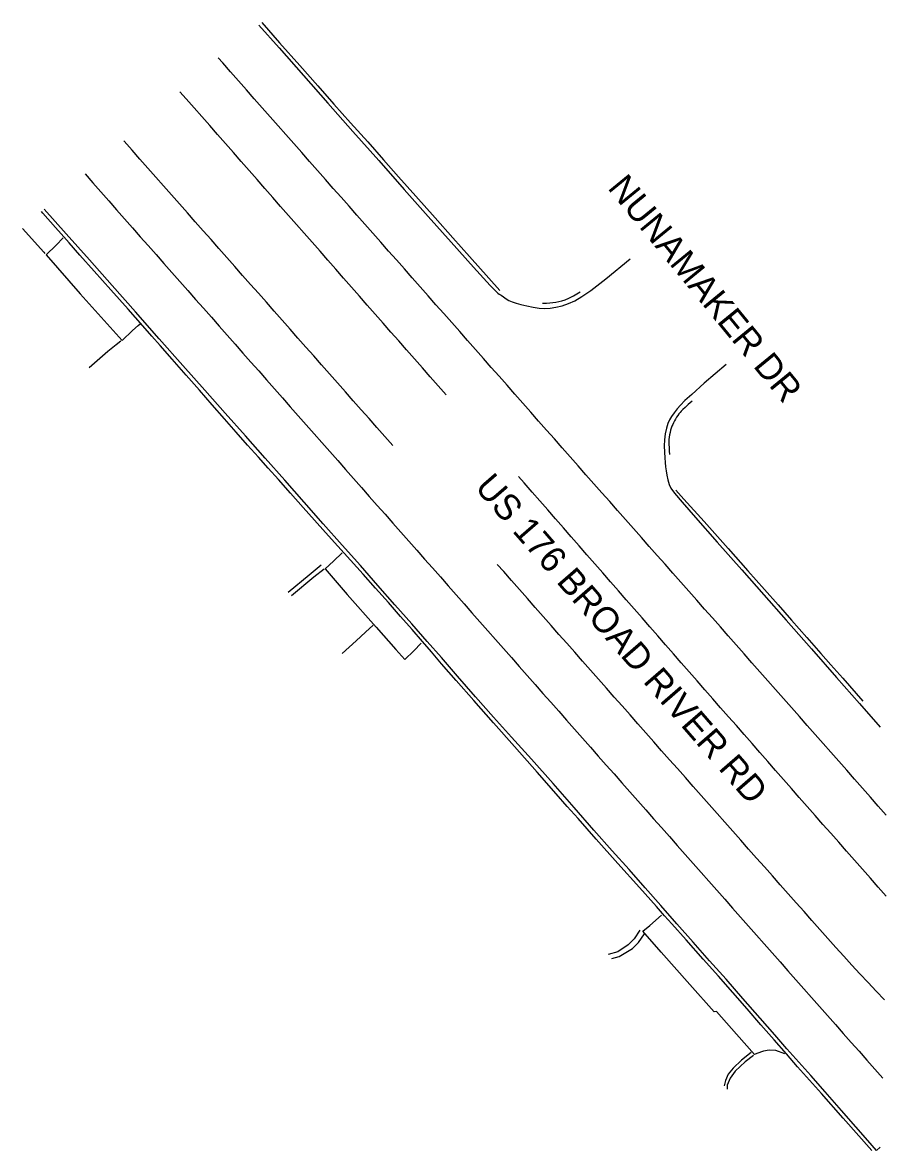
# Model space of a CAD drawing. Extents: x 1970211 to 1973046, y 801032 to 804001.
# Drawn here: x 1970210.9 to 1970390.1, y 803765.1 to 804001.2 of the extents above; entities that cross this region are included whole.
import ezdxf

# ---------------------------------------------------------------- set-up
doc = ezdxf.new("R2010")
doc.units = 0
for name, color, linetype in [('RD_EX_Conc', 7, 'Continuous'), ('RD_EX_Road', 7, 'Continuous'), ('RD_EX_Road_Paint', 7, 'Continuous'), ('RD_TX_RoadID', 7, 'Continuous')]:
    doc.layers.add(name, color=color, linetype=linetype)

msp = doc.modelspace()

# ---------------------------------------------------------------- linework, layer by layer
at = {"layer": 'RD_EX_Conc'}
for points in [[(1970261.01, 804001.2), (1970264.73, 803996.97), (1970268.97, 803992.18), (1970272.72, 803987.95), (1970276.12, 803984.12), (1970279.61, 803980.21), (1970283.19, 803976.2), (1970286.52, 803972.46), (1970289.65, 803968.92), (1970293.25, 803964.87), (1970297.29, 803960.31), (1970301.03, 803956.11), (1970304.48, 803952.22), (1970308.53, 803947.68), (1970310.84, 803945.11)], [(1970388.74, 803765.05), (1970382.78, 803771.78), (1970378.2, 803776.95), (1970373.21, 803782.59), (1970370.86, 803785.25), (1970368.3, 803788.19), (1970365.55, 803791.36), (1970362.62, 803794.69), (1970359.62, 803798.11), (1970356.62, 803801.53), (1970353.43, 803805.13), (1970349.88, 803809.13), (1970346.87, 803812.49), (1970345.35, 803814.19), (1970343.65, 803816.11), (1970340.08, 803820.11), (1970335.58, 803825.16), (1970331.03, 803830.26), (1970327.24, 803834.52), (1970324.97, 803837.08), (1970322.64, 803839.73), (1970318.64, 803844.28), (1970313.94, 803849.61), (1970309.51, 803854.61), (1970305.42, 803859.24), (1970301.72, 803863.46), (1970298.66, 803866.96), (1970296.53, 803869.45), (1970294.68, 803871.6), (1970292.51, 803874.12), (1970290.08, 803876.88), (1970287.51, 803879.81), (1970284.85, 803882.79), (1970282.21, 803885.71), (1970279.56, 803888.61), (1970276.92, 803891.56), (1970274.37, 803894.4), (1970272.04, 803897.02), (1970269.68, 803899.67), (1970267.05, 803902.65), (1970264.5, 803905.54), (1970262.35, 803907.93), (1970260.3, 803910.2), (1970258.04, 803912.75), (1970255.64, 803915.46), (1970253.19, 803918.26), (1970250.64, 803921.16), (1970247.96, 803924.2), (1970245.16, 803927.38), (1970242.25, 803930.69), (1970239.7, 803933.59), (1970237.98, 803935.57), (1970236.08, 803937.73), (1970232.99, 803941.19), (1970229.38, 803945.22), (1970225.93, 803949.12), (1970222.92, 803952.53), (1970220.64, 803955.11), (1970218.97, 803956.99), (1970217.8, 803958.29), (1970215.15, 803961.28), (1970214.85, 803961.62)], [(1970210.9, 803958.1), (1970215.36, 803953.1), (1970215.57, 803952.85)], [(1970219.39, 803956.14), (1970217.97, 803954.57), (1970215.82, 803952.57), (1970222.99, 803944.43), (1970231.73, 803934.64), (1970233.9, 803936.74), (1970235.08, 803937.76), (1970235.56, 803938.13)], [(1970319.78, 803942.42), (1970320.64, 803942.44), (1970321.34, 803942.49), (1970321.97, 803942.58), (1970322.6, 803942.67), (1970323.23, 803942.78), (1970323.86, 803942.95), (1970324.54, 803943.17), (1970325.29, 803943.48), (1970326.29, 803943.99), (1970327.7, 803944.84)], [(1970351.12, 803921.9), (1970350.3, 803921.2), (1970349.65, 803920.63), (1970349.17, 803920.18), (1970348.84, 803919.86), (1970348.6, 803919.59), (1970348.35, 803919.28), (1970348.11, 803918.93), (1970347.86, 803918.55), (1970347.63, 803918.16), (1970347.42, 803917.78), (1970347.23, 803917.42), (1970347.07, 803917.07), (1970346.91, 803916.71), (1970346.77, 803916.31), (1970346.63, 803915.88), (1970346.5, 803915.4), (1970346.39, 803914.91), (1970346.3, 803914.42), (1970346.26, 803913.92), (1970346.24, 803913.42), (1970346.25, 803912.88), (1970346.29, 803912.25), (1970346.34, 803911.53), (1970346.42, 803910.73)], [(1970347.74, 803903.3), (1970349.42, 803901.41), (1970353.62, 803896.72), (1970358.66, 803891.1), (1970362.82, 803886.42), (1970366.26, 803882.52), (1970369.12, 803879.27), (1970371.91, 803876.1), (1970375.13, 803872.47), (1970378.11, 803869.11), (1970380.18, 803866.76), (1970382.66, 803863.92), (1970386.9, 803859.09)], [(1970277.84, 803890.15), (1970276.04, 803888.45), (1970274.26, 803886.84), (1970278.85, 803881.44), (1970284.98, 803874.6), (1970289.04, 803869.96), (1970290.96, 803867.83), (1970292.81, 803869.69), (1970294.4, 803871.27)], [(1970266.53, 803881.97), (1970270.95, 803885.57), (1970273.45, 803887.67)], [(1970370.53, 803785.3), (1970368.68, 803785.96), (1970367.28, 803786.08), (1970366.1, 803785.85), (1970364.7, 803785.38), (1970364.22, 803785.13), (1970360.43, 803789.38), (1970356.2, 803794.15), (1970355.71, 803794.07), (1970350.62, 803799.8), (1970344.65, 803806.54), (1970340.77, 803810.98), (1970342.25, 803812.15), (1970344.68, 803814.31)], [(1970340.16, 803811.14), (1970339.01, 803809.39), (1970337.74, 803808.1), (1970335.55, 803806.62), (1970333.55, 803806.11)], [(1970363.98, 803784.91), (1970362.2, 803783.62), (1970360.14, 803781.68), (1970359.08, 803780.19), (1970358.49, 803778.7), (1970358.44, 803777.91)]]:
    msp.add_lwpolyline(points, dxfattribs=at)
at = {"layer": 'RD_EX_Road'}
for points in [[(1970260.41, 804000.67), (1970264.66, 803995.88), (1970269.73, 803990.14), (1970274.85, 803984.33), (1970280.09, 803978.39), (1970285.49, 803972.29), (1970290.83, 803966.28), (1970295.86, 803960.6), (1970300.66, 803955.21), (1970305.34, 803950.01), (1970308.86, 803946.15), (1970310.2, 803944.72), (1970310.45, 803944.52), (1970310.73, 803944.33), (1970311.1, 803944.09), (1970311.6, 803943.75), (1970312.18, 803943.37), (1970312.76, 803943.04), (1970313.43, 803942.74), (1970314.25, 803942.48), (1970315.26, 803942.2), (1970316.5, 803941.88), (1970317.81, 803941.59), (1970319.07, 803941.41), (1970320.26, 803941.35), (1970321.38, 803941.4), (1970322.55, 803941.59), (1970323.88, 803941.92), (1970325.26, 803942.39), (1970326.56, 803942.96), (1970328.04, 803943.82), (1970329.94, 803945.12), (1970333.04, 803947.54), (1970338.13, 803951.74)], [(1970390.5, 803765.74), (1970389.77, 803765.07), (1970387.94, 803767.13), (1970385.41, 803769.99), (1970382.38, 803773.43), (1970378.99, 803777.31), (1970375.99, 803780.71), (1970373.46, 803783.56), (1970370.99, 803786.35), (1970368.45, 803789.24), (1970365.38, 803792.75), (1970361.78, 803796.85), (1970358.23, 803800.88), (1970354.8, 803804.75), (1970351.36, 803808.63), (1970347.9, 803812.53), (1970344.54, 803816.33), (1970341.28, 803820.04), (1970337.92, 803823.84), (1970334.41, 803827.79), (1970330.57, 803832.13), (1970326.39, 803836.88), (1970321.99, 803841.86), (1970317.48, 803846.96), (1970313.33, 803851.6), (1970309.53, 803855.79), (1970305.75, 803860.05), (1970301.97, 803864.38), (1970298.61, 803868.24), (1970295.63, 803871.64), (1970292.4, 803875.3), (1970288.88, 803879.29), (1970285.29, 803883.35), (1970281.66, 803887.49), (1970277.85, 803891.8), (1970273.88, 803896.28), (1970269.86, 803900.81), (1970265.82, 803905.37), (1970261.72, 803910), (1970257.56, 803914.69), (1970253.36, 803919.42), (1970249.1, 803924.23), (1970244.49, 803929.43), (1970239.54, 803935.01), (1970234.57, 803940.61), (1970229.66, 803946.14), (1970224.9, 803951.49), (1970220.06, 803956.94), (1970215.44, 803962.14)], [(1970231.5, 803934.48), (1970230.52, 803933.69), (1970228.79, 803932.32), (1970224.88, 803928.93)], [(1970358.23, 803929.61), (1970353.66, 803925.67), (1970351.04, 803923.36), (1970349.62, 803922.04), (1970348.67, 803921.08), (1970347.98, 803920.29), (1970347.36, 803919.5), (1970346.83, 803918.74), (1970346.42, 803918.04), (1970346.07, 803917.25), (1970345.75, 803916.25), (1970345.48, 803915.1), (1970345.34, 803913.85), (1970345.29, 803912.56), (1970345.33, 803911.26), (1970345.4, 803910.07), (1970345.47, 803909.08), (1970345.56, 803908.2), (1970345.67, 803907.33), (1970345.83, 803906.42), (1970346.04, 803905.44), (1970346.32, 803904.5), (1970346.68, 803903.73), (1970347.47, 803902.65), (1970349.01, 803900.78), (1970351.81, 803897.57), (1970356.36, 803892.42), (1970361.52, 803886.6), (1970366.16, 803881.36), (1970370.84, 803876.07), (1970376.1, 803870.1), (1970381.39, 803864.06), (1970386.18, 803858.6), (1970390.49, 803853.69)], [(1970274.07, 803886.73), (1970271.93, 803885.08), (1970267.2, 803881.2)], [(1970277.85, 803869.11), (1970280.79, 803871.76), (1970282.71, 803873.54), (1970284.33, 803875.04)], [(1970334.34, 803805.22), (1970335.83, 803805.64), (1970338.65, 803807.31), (1970339.93, 803808.62), (1970341.17, 803810.37)], [(1970363.51, 803785.58), (1970361.49, 803783.98), (1970359.7, 803782.27), (1970358.67, 803781.02), (1970358.09, 803779.71), (1970357.87, 803778.55)]]:
    msp.add_lwpolyline(points, dxfattribs=at)
at = {"layer": 'RD_EX_Road_Paint'}
for points in [[(1970391.76, 803835.28), (1970390.11, 803837.15), (1970388.45, 803839.03), (1970386.8, 803840.9), (1970385.15, 803842.78), (1970383.5, 803844.66), (1970381.84, 803846.53), (1970380.19, 803848.41), (1970378.54, 803850.28), (1970376.89, 803852.16), (1970375.23, 803854.03), (1970373.58, 803855.91), (1970371.93, 803857.79), (1970370.27, 803859.66), (1970368.62, 803861.54), (1970366.97, 803863.41), (1970365.32, 803865.29), (1970363.66, 803867.16), (1970362.01, 803869.04), (1970360.36, 803870.92), (1970358.7, 803872.79), (1970357.05, 803874.66), (1970355.39, 803876.54), (1970353.74, 803878.41), (1970352.08, 803880.28), (1970350.43, 803882.16), (1970348.77, 803884.03), (1970347.11, 803885.9), (1970345.46, 803887.78), (1970343.8, 803889.65), (1970342.15, 803891.52), (1970340.49, 803893.39), (1970338.83, 803895.27), (1970337.18, 803897.14), (1970335.52, 803899.01), (1970333.87, 803900.89), (1970332.21, 803902.76), (1970330.56, 803904.63), (1970328.9, 803906.51), (1970327.25, 803908.38), (1970325.6, 803910.26), (1970323.94, 803912.13), (1970322.29, 803914.01), (1970320.64, 803915.89), (1970318.98, 803917.76), (1970317.33, 803919.64), (1970315.68, 803921.51), (1970314.03, 803923.39), (1970312.37, 803925.26), (1970310.72, 803927.14), (1970309.07, 803929.01), (1970307.41, 803930.89), (1970305.76, 803932.76), (1970304.1, 803934.64), (1970302.45, 803936.51), (1970300.79, 803938.38), (1970299.14, 803940.26), (1970297.48, 803942.13), (1970295.83, 803944), (1970294.18, 803945.88), (1970292.52, 803947.75), (1970290.87, 803949.63), (1970289.21, 803951.5), (1970287.56, 803953.37), (1970285.9, 803955.25), (1970284.25, 803957.12), (1970282.59, 803958.99), (1970280.94, 803960.87), (1970279.28, 803962.74), (1970277.63, 803964.61), (1970275.97, 803966.49), (1970274.32, 803968.36), (1970272.67, 803970.24), (1970271.01, 803972.11), (1970269.36, 803973.99), (1970267.7, 803975.86), (1970266.05, 803977.74), (1970264.4, 803979.61), (1970262.74, 803981.49), (1970261.09, 803983.36), (1970259.44, 803985.24), (1970257.78, 803987.11), (1970256.13, 803988.99), (1970254.48, 803990.86), (1970252.82, 803992.74), (1970251.89, 803993.8)], [(1970299.59, 803923.26), (1970297.94, 803925.14), (1970296.29, 803927.02), (1970294.64, 803928.9), (1970292.99, 803930.77), (1970291.34, 803932.65), (1970289.69, 803934.53), (1970288.04, 803936.41), (1970286.39, 803938.29), (1970284.74, 803940.17), (1970283.09, 803942.05), (1970281.44, 803943.92), (1970279.79, 803945.8), (1970278.14, 803947.68), (1970276.49, 803949.56), (1970274.85, 803951.44), (1970273.2, 803953.32), (1970271.55, 803955.2), (1970269.9, 803957.07), (1970268.25, 803958.95), (1970266.6, 803960.83), (1970264.95, 803962.71), (1970263.3, 803964.59), (1970261.65, 803966.47), (1970260, 803968.35), (1970258.35, 803970.22), (1970256.7, 803972.1), (1970255.05, 803973.98), (1970253.4, 803975.86), (1970251.76, 803977.74), (1970250.11, 803979.62), (1970248.46, 803981.5), (1970246.81, 803983.37), (1970245.16, 803985.25), (1970243.87, 803986.72)], [(1970288.44, 803912.65), (1970286.78, 803914.53), (1970285.13, 803916.4), (1970283.47, 803918.27), (1970281.82, 803920.15), (1970280.16, 803922.02), (1970278.51, 803923.9), (1970276.85, 803925.77), (1970275.2, 803927.64), (1970273.54, 803929.52), (1970271.89, 803931.39), (1970270.23, 803933.26), (1970268.58, 803935.14), (1970266.92, 803937.01), (1970265.27, 803938.88), (1970263.61, 803940.76), (1970261.96, 803942.63), (1970260.3, 803944.51), (1970258.65, 803946.38), (1970256.99, 803948.25), (1970255.34, 803950.13), (1970253.69, 803952), (1970252.03, 803953.87), (1970250.38, 803955.75), (1970248.72, 803957.62), (1970247.07, 803959.5), (1970245.41, 803961.37), (1970243.76, 803963.24), (1970242.1, 803965.12), (1970240.45, 803966.99), (1970238.79, 803968.86), (1970237.14, 803970.74), (1970235.48, 803972.61), (1970233.83, 803974.48), (1970232.17, 803976.36), (1970232.12, 803976.41)], [(1970223.99, 803969.5), (1970225.64, 803967.62), (1970227.29, 803965.75), (1970228.95, 803963.87), (1970230.6, 803962), (1970232.26, 803960.12), (1970233.91, 803958.25), (1970235.56, 803956.37), (1970237.22, 803954.5), (1970238.87, 803952.62), (1970240.52, 803950.75), (1970242.18, 803948.87), (1970243.83, 803947), (1970245.48, 803945.12), (1970247.14, 803943.25), (1970248.79, 803941.37), (1970250.44, 803939.5), (1970252.1, 803937.62), (1970253.75, 803935.75), (1970255.4, 803933.87), (1970257.06, 803932), (1970258.71, 803930.12), (1970260.37, 803928.25), (1970262.02, 803926.37), (1970263.67, 803924.5), (1970265.33, 803922.62), (1970266.98, 803920.75), (1970268.63, 803918.87), (1970270.29, 803917), (1970271.94, 803915.12), (1970273.59, 803913.25), (1970275.25, 803911.37), (1970276.9, 803909.5), (1970278.55, 803907.62), (1970280.21, 803905.75), (1970281.86, 803903.87), (1970283.51, 803902), (1970285.17, 803900.12), (1970286.82, 803898.25), (1970288.48, 803896.37), (1970290.13, 803894.5), (1970291.78, 803892.62), (1970293.44, 803890.75), (1970295.09, 803888.87), (1970296.74, 803887), (1970298.4, 803885.12), (1970300.05, 803883.25), (1970301.7, 803881.37), (1970303.36, 803879.5), (1970305.01, 803877.62), (1970306.66, 803875.75), (1970308.32, 803873.87), (1970309.97, 803872), (1970311.62, 803870.12), (1970313.28, 803868.25), (1970314.93, 803866.37), (1970316.58, 803864.5), (1970318.24, 803862.63), (1970319.89, 803860.75), (1970321.55, 803858.88), (1970323.2, 803857), (1970324.85, 803855.13), (1970326.51, 803853.25), (1970328.16, 803851.38), (1970329.81, 803849.5), (1970331.47, 803847.63), (1970333.12, 803845.75), (1970334.78, 803843.88), (1970336.43, 803842.01), (1970338.09, 803840.13), (1970339.74, 803838.26), (1970341.4, 803836.39), (1970343.05, 803834.51), (1970344.71, 803832.64), (1970346.37, 803830.77), (1970348.02, 803828.89), (1970349.68, 803827.02), (1970351.33, 803825.15), (1970352.99, 803823.27), (1970354.64, 803821.4), (1970356.3, 803819.53), (1970357.95, 803817.65), (1970359.61, 803815.78), (1970361.26, 803813.91), (1970362.92, 803812.03), (1970364.58, 803810.16), (1970366.23, 803808.29), (1970367.89, 803806.41), (1970369.54, 803804.54), (1970371.2, 803802.67), (1970372.85, 803800.79), (1970374.51, 803798.92), (1970376.16, 803797.05), (1970377.82, 803795.17), (1970379.48, 803793.3), (1970381.13, 803791.43), (1970382.79, 803789.55), (1970384.44, 803787.68), (1970386.1, 803785.81), (1970387.75, 803783.93), (1970389.41, 803782.06), (1970391.06, 803780.19)], [(1970391.76, 803818.32), (1970390.11, 803820.2), (1970388.45, 803822.07), (1970386.8, 803823.95), (1970385.15, 803825.82), (1970383.49, 803827.7), (1970381.84, 803829.57), (1970380.19, 803831.45), (1970378.53, 803833.32), (1970376.88, 803835.2), (1970375.23, 803837.07), (1970373.57, 803838.95), (1970371.92, 803840.82), (1970370.27, 803842.7), (1970368.62, 803844.58), (1970366.98, 803846.47), (1970365.33, 803848.35), (1970363.68, 803850.23), (1970362.04, 803852.11), (1970360.39, 803853.99), (1970358.74, 803855.87), (1970357.1, 803857.75), (1970355.45, 803859.63), (1970353.8, 803861.51), (1970352.15, 803863.39), (1970350.51, 803865.27), (1970348.86, 803867.15), (1970347.22, 803869.04), (1970345.57, 803870.92), (1970343.92, 803872.8), (1970342.28, 803874.68), (1970340.63, 803876.56), (1970338.99, 803878.44), (1970337.34, 803880.33), (1970335.69, 803882.21), (1970334.05, 803884.09), (1970332.4, 803885.97), (1970330.75, 803887.85), (1970329.11, 803889.73), (1970327.46, 803891.62), (1970325.82, 803893.5), (1970324.17, 803895.38), (1970322.53, 803897.27), (1970320.89, 803899.15), (1970319.24, 803901.03), (1970317.6, 803902.91), (1970315.95, 803904.8), (1970314.77, 803906.15)], [(1970391.4, 803796.56), (1970389.69, 803798.38), (1970387.98, 803800.21), (1970386.28, 803802.04), (1970384.57, 803803.87), (1970382.88, 803805.7), (1970381.21, 803807.57), (1970379.55, 803809.44), (1970377.89, 803811.31), (1970376.23, 803813.18), (1970374.57, 803815.05), (1970372.91, 803816.92), (1970371.25, 803818.78), (1970369.59, 803820.65), (1970367.93, 803822.52), (1970366.28, 803824.4), (1970364.62, 803826.27), (1970362.96, 803828.14), (1970361.31, 803830.01), (1970359.65, 803831.89), (1970357.99, 803833.76), (1970356.34, 803835.63), (1970354.68, 803837.5), (1970353.02, 803839.37), (1970351.37, 803841.25), (1970349.71, 803843.12), (1970348.05, 803844.99), (1970346.39, 803846.86), (1970344.74, 803848.74), (1970343.08, 803850.61), (1970341.43, 803852.48), (1970339.77, 803854.36), (1970338.12, 803856.23), (1970336.47, 803858.11), (1970334.81, 803859.98), (1970333.16, 803861.86), (1970331.5, 803863.73), (1970329.85, 803865.61), (1970328.2, 803867.48), (1970326.54, 803869.36), (1970324.89, 803871.23), (1970323.24, 803873.11), (1970321.58, 803874.98), (1970319.93, 803876.86), (1970318.28, 803878.73), (1970316.62, 803880.61), (1970314.97, 803882.48), (1970313.32, 803884.36), (1970311.67, 803886.24), (1970310.33, 803887.75)]]:
    msp.add_lwpolyline(points, dxfattribs=at)

# ---------------------------------------------------------------- texts
at = {"layer": 'RD_TX_RoadID'}
for s, rotation, p in [('NUNAMAKER DR', 309.2924, (1970333.27, 803966.52)), ('US 176 BROAD RIVER RD', 310.9626, (1970305.43, 803903.79))]:
    msp.add_text(s, height=5.4, rotation=rotation, dxfattribs=at).set_placement(p)

doc.saveas('drawing.dxf')
